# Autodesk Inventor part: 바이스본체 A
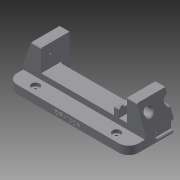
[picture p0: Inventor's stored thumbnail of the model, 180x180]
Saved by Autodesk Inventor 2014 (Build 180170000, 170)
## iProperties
Created: 2017-04
Part Number: 바이스본체 A
Material: 일반
Document SubType Name: Modeling
Designer: mduedu
Density: 1 g/cm^3
Appearance: 기본값
Author: mduedu
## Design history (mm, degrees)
sketch "스케치1"
  geometry: L1 (-75, 0)-(75, 0); L2 (-75, 0)-(-75, 17); L3 (-53, 17)-(53, 17); L4 (75, 17)-(75, 0); L5 (-75, 17)-(-65.173, 44); L6 (-65.173, 44)-(-53, 44); L7 (-53, 44)-(-53, 17); L8 (0, 0)-(0, 17); L9 (75, 17)-(65.173, 44); L10 (65.173, 44)-(53, 44); L11 (53, 44)-(53, 17); 1 further point
  constraints: 22 end point, 4 perpendicular, 2 horizontal alignment, 2 midpoint, 2 symmetric about line, 1 coincident, 1 collinear, 1 horizontal, 1 vertical
  dimensions: "d0" = 150 distance of L1.start L1.end; "d1" = 17 distance of L1.start L2.end; "d2" = 27 distance of L3.start L6.end; "d3" = 22 distance of L3.start L2.end; "d4" = 70 deg angle of L3 L5; "d54" = 20 deg angle of L9 L4
extrude "돌출1" new body sketch "스케치1" stored distance "d5" = 70; taper "d6" = 0 deg
sketch "스케치2"
  geometry: L1 (0, 70)-(106, 70) reference; L2 (106, 70)-(106, 0) reference; L3 (106, 0)-(0, 0) reference; L4 (0, 47)-(106, 47); L5 (106, 47)-(106, 23); L6 (106, 23)-(0, 23); L7 (0, 23)-(0, 47); L8 (0, 70)-(0, 0) reference; 2 further points
  constraints: 8 end point, 2 parallel, 2 point on line, 1 horizontal, 1 horizontal alignment, 1 midpoint, 1 perpendicular
  dimensions: "d7" = 24 distance between parallel lines of L6 L4
extrude "돌출2" cut sketch "스케치2" stored distance "d9" = 70; taper "d10" = 0 deg
sketch "스케치3"
  geometry: L1 (22, -23)-(128, -23) reference; L2 (128, -47)-(22, -47) reference; L3 (22, -18)-(128, -18); L4 (128, -52)-(22, -52); L5 (22, -18)-(22, -52); L6 (128, -18)-(128, -52); 1 further point
  constraints: 8 end point, 3 parallel, 2 point on line, 1 perpendicular
  dimensions: "d11" = 5 distance between parallel lines of L3 L1; "d12" = 5 distance between parallel lines of L4 L2
extrude "돌출3" cut sketch "스케치3" distance "d13" = 12; taper "d14" = 0 deg
fillet "모깎기1" dims "d15" = 3, "d16" = 3
sketch "스케치4"
  geometry: L1 (103, 23)-(3, 23) reference; L2 (0, 26)-(0, 0) reference; L3 (106, 0)-(0, 0) reference; L4 (106, 26)-(106, 0) reference; L5 (96, 0)-(90, 0); L6 (90, 0)-(90, 19.5); L7 (96, 19.5)-(96, 0); L8 (90, 19.5)-(96, 19.5); A1 r 3 centre (3, 26) between (0, 26) and (3, 23) reference; A2 r 3 centre (103, 26) between (103, 23) and (106, 26) reference; 1 further point
  constraints: 8 end point, 2 perpendicular, 1 horizontal, 1 parallel, 1 point on line
  dimensions: "d17" = 10 distance between parallel lines of L7 L4; "d18" = 6 distance between parallel lines of L7 L6; "d27" = 3.5 distance between parallel lines of L8 L1
extrude "돌출4" join sketch "스케치4" distance "d19" = 12; taper "d20" = 0 deg
chamfer "모따기1" distance "d21" = 3; stored, may be unused: second distance "d22" = 2, angle "d23" = 45 deg
chamfer "모따기2" distance "d24" = 3; stored, may be unused: second distance "d25" = 2, angle "d26" = 45 deg
sketch "스케치5"
  geometry: L1 (-15.5, 35.8)-(-15.5, -25.8) reference; L2 (19.5, 0)-(0, 0) reference; C1 r 6.5 at (9.5, 15); 1 further point
  constraints: 1 centre point
  dimensions: "d28" = 13 diameter of C1; "d30" = 15 distance from line of C1.centre L2; "d31" = 25 distance from line of C1.centre L1
extrude "돌출5" cut sketch "스케치5" stored distance "d32" = 12; taper "d33" = 0 deg
sketch "스케치6"
  geometry: C1 r 5 at (-10, 15); C2 r 5 at (-60, 15); A1 r 6.5 centre (-10, 15) between (-15.766, 12) and (-4.234, 12) reference; A2 r 6.5 centre (-60, 15) between (-65.766, 12) and (-54.234, 12) reference; 1 further point
  constraints: 2 centre point, 2 coincident
  dimensions: "d34" = 10 diameter of C1; "d35" = 10 diameter of C2 (= d34)
extrude "돌출6" cut sketch "스케치6" stored distance "d36" = 12; taper "d37" = 0 deg
chamfer "모따기3" distance "d38" = 1; stored, may be unused: second distance "d39" = 2, angle "d40" = 45 deg
chamfer "모따기4" distance "d41" = 1; stored, may be unused: second distance "d42" = 2, angle "d43" = 45 deg
sketch "스케치7"
  geometry: L1 (-35, 35.8)-(-35, -25.8) reference; L2 (-70, 0)-(0, 0) reference; C1 r 5 at (-35, 15); 1 further point
  constraints: 1 centre point, 1 point on line
  dimensions: "d44" = 10 diameter of C1; "d45" = 15 distance from line of C1.centre L2
extrude "돌출7" cut sketch "스케치7" stored distance "d46" = 12; taper "d47" = 0 deg
chamfer "모따기5" distance "d48" = 1; stored, may be unused: second distance "d49" = 2, angle "d50" = 45 deg
node "작업축1"
sketch "스케치8"
  geometry: L1 (-105, 32)-(105, 32) reference; L2 (58, 32)-(64, 32); L3 (64, 32)-(64, 40); L4 (64, 40)-(58, 40); L5 (58, 40)-(58, 32); L6 (53, 38)-(53, 26) reference; 1 further point
  constraints: 8 end point, 2 parallel, 1 horizontal, 1 perpendicular, 1 point on line
  dimensions: "d51" = 5 distance from line of L6 L2.start; "d52" = 6 distance of L3.end L4.end; "d53" = 16 diameter of L4 L1
revolve "회전1" sketch "스케치8" stored, may be unused: angle "d55" = 90 deg
fillet "모깎기2"
chamfer "모따기6" distance "d56" = 1; stored, may be unused: second distance "d57" = 2, angle "d58" = 45 deg
sketch "스케치9"
  geometry: L1 (17.5, 3)-(52.5, 3); L2 (52.5, 13)-(17.5, 13); L3 (70, 0)-(0, 0) reference; L4 (17.5, 8)-(52.5, 8); A1 r 5 centre (17.5, 8) between (17.5, 13) and (17.5, 3); A2 r 5 centre (52.5, 8) between (52.5, 3) and (52.5, 13); 3 further points
  constraints: 6 end point, 4 point on circle, 3 tangent, 2 centre point, 2 midpoint, 2 parallel, 1 horizontal, 1 vertical alignment
  dimensions: "d59" = 35 distance of L4.start L4.end; "d61" = 5 radius of A2; "d62" = 8 distance between parallel lines of L3 L4
extrude "돌출8" cut sketch "스케치9" distance "d63" = 3; taper "d64" = 0 deg
chamfer "모따기7" distance "d65" = 1; stored, may be unused: second distance "d66" = 2, angle "d67" = 45 deg
chamfer "모따기8" distance "d68" = 1; stored, may be unused: second distance "d69" = 2, angle "d70" = 45 deg
feature "분할1"
sketch "스케치10"
  geometry: L1 (35, 27)-(0, 27) reference; L2 (0, 0)-(0, 27) reference; 1 further point
  dimensions: "d85" = 11.5 distance from line of point (12, 15.5) L1; "d86" = 12 distance from line of point (12, 15.5) L2
hole "구멍1" sketch "스케치10" at (12, 15.5) diameter "d71" = 3.242; stored, may be unused: countersink angle "d75" = 90 deg, drill point angle "d77" = 120 deg; dims "d72" = 8, "d73" = 4, "d74" = 2, "d76" = 10
sketch "스케치11"
  geometry: A1 r 5 centre (17.5, 8) between (17.5, 13) and (17.5, 3) reference; 1 further point
  constraints: 1 coincident
hole "구멍3" sketch "스케치11" at (17.5, 8) diameter "d78" = 2.459; stored, may be unused: countersink angle "d82" = 90 deg, drill point angle "d84" = 120 deg; dims "d79" = 4.5, "d80" = 4, "d81" = 2, "d83" = 6
sketch "스케치13"
  geometry: L1 (75, 0)-(75, 35) reference; L2 (-75, 0)-(-75, 35) reference; L3 (-75, 35)-(75, 35); L4 (75, 35)-(75, 55); L5 (75, 55)-(-75, 55); L6 (-75, 55)-(-75, 35); 1 further point
  constraints: 8 end point, 2 parallel, 1 horizontal, 1 perpendicular, 1 point on line
  dimensions: "d90" = 20 distance between parallel lines of L5 L3; "d94" = 150 distance of L4.end L5.end (derived)
extrude "돌출9" join sketch "스케치13" distance "d92" = 10; taper "d93" = 0 deg
sketch "스케치14"
  geometry: L1 (-75, -35)-(-75, -55) reference; L2 (75, -55)-(75, -35) reference; L3 (-75, -45)-(75, -45); 3 further points
  constraints: 2 end point, 2 midpoint, 2 point on line
  dimensions: "d95" = 50 horizontal distance of point (-50, -45) point (0, 0); "d96" = 100 distance of point (50, -45) point (-50, -45)
fillet "모깎기3" dims "d97" = 12
chamfer "모따기9" distance "d98" = 1; stored, may be unused: second distance "d99" = 2, angle "d100" = 45 deg
hole "구멍4" sketch "스케치14" diameter "d101" = 4.134; stored, may be unused: countersink angle "d105" = 90 deg, drill point angle "d107" = 118 deg; dims "d102" = 6, "d103" = 10, "d104" = 4, "d106" = 8
sketch "스케치15"
  geometry: L1 (0, 0)-(126, 0) reference; 3 further points
  constraints: 1 midpoint, 1 vertical alignment, 1 other
  dimensions: "d109" = 5 distance from line of point (63, 5) L1
feature "엠보싱2" sketch "스케치15" dims "d0" = 150, "d1" = 17, "d2" = 27, "d3" = 22, "d4" = 70 deg, "d54" = 20 deg, "d110" = 0.5, "d111" = 0
node "솔리드1"
mirror "대칭1"
mirror "대칭2"
mirror "대칭3"
mirror "대칭4"
node "투영된 루프1"
